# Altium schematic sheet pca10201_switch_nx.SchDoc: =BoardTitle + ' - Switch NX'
size A3; Organization: Nordic Semiconductor; DocumentNumber: 10; SheetNumber: 10; SheetTotal: 10; CompanyName: Nordic Semiconductor; DocumentSize: A4
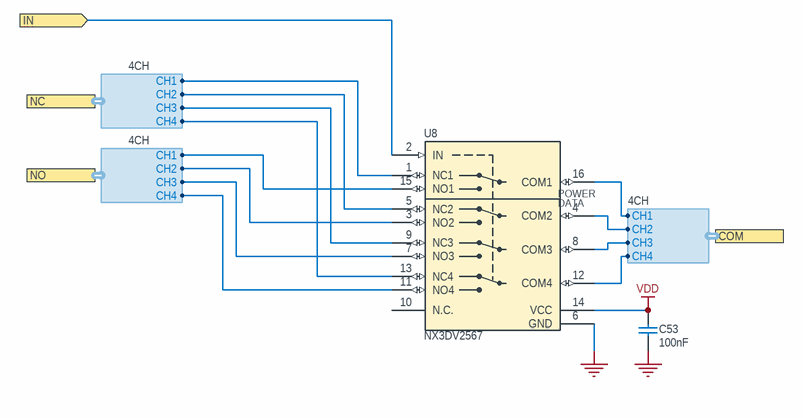
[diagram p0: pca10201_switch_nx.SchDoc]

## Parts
C53  100nF  [CAPC0603X03L_C]
U8  NX3DV2567  [XQFN40P180X260X50-16N]

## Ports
COM (harness 4CH), IN (in), NC (harness 4CH), NO (harness 4CH)

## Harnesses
4CH: CH1, CH2, CH3, CH4

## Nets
GND: C53.2 U8.6(GND)
VDD: C53.1 U8.14(VCC)
IN: U8.2(IN) ; port IN
NetU8_1: U8.1(NC1) ; port NC.CH1
NetU8_3: U8.3(NO2) ; port NO.CH2
NetU8_4: U8.4(COM2) ; port COM.CH2
NetU8_5: U8.5(NC2) ; port NC.CH2
NetU8_7: U8.7(NO3) ; port NO.CH3
NetU8_8: U8.8(COM3) ; port COM.CH3
NetU8_9: U8.9(NC3) ; port NC.CH3
NetU8_11: U8.11(NO4) ; port NO.CH4
NetU8_12: U8.12(COM4) ; port COM.CH4
NetU8_13: U8.13(NC4) ; port NC.CH4
NetU8_15: U8.15(NO1) ; port NO.CH1
NetU8_16: U8.16(COM1) ; port COM.CH1

Not connected (* = marked no-connect by the designer): U8 10(N.C.)

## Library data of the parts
C53 = C0201-100n: Capacitor, X5R, ±10%, 100nF, 16V; Manufacturer: N.A.; Part number IPS: 00000001248, 00000002505; Part number Norautron: 262071862; Part number NEMS: 100200078; Pad Count: 2; Component Status: Active
U8 = NX3DV2567GU: Low-ohmic four-pole double-throw analog switch; Manufacturer: NXP Semiconductors; Part number IPS: 00000007816; Part number NEMS: 101900290; Note: N.A.; Artikkelnr Noca: 15079317; Pad Count: 16; Component Status: Active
